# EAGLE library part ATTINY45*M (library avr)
MICROCONTROLLER 4 Kbytes FLASH 256 bytes EEPROM 256 bytes RAM 4-channel 10 bit ADC USI
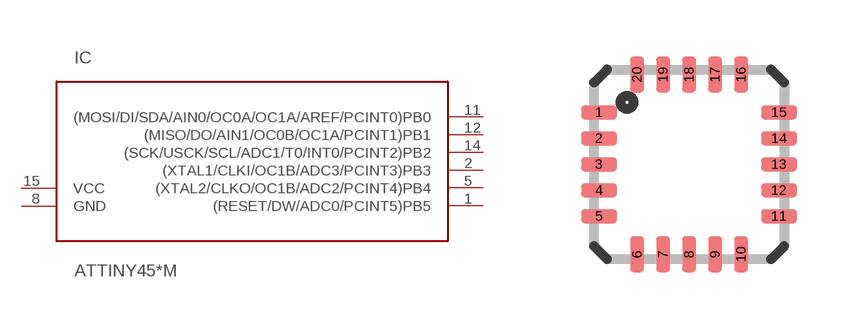
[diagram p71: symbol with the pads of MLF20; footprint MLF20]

Designator prefix IC

## ATTINY45-20M, ATTINY45V-10M  [MLF20]
1  (RESET/DW/ADC0/PCINT5)PB5
2  (XTAL1/CLKI/OC1B/ADC3/PCINT3)PB3
3  P$1  nc
4  P$2  nc
5  (XTAL2/CLKO/OC1B/ADC2/PCINT4)PB4
6  P$3  nc
7  P$4  nc
8  GND
9  P$5  nc
10  P$6  nc
11  (MOSI/DI/SDA/AIN0/OC0A/OC1A/AREF/PCINT0)PB0
12  (MISO/DO/AIN1/OC0B/OC1A/PCINT1)PB1
13  P$7  nc
14  (SCK/USCK/SCL/ADC1/T0/INT0/PCINT2)PB2
15  VCC
16  P$8  nc
17  P$9  nc
18  P$10  nc
19  P$11  nc
20  P$12  nc

## Footprint MLF20 (pad centres in mm)
HP-VFQFP-N20 Micro Lead Frame package (MLF)
smd 0.9 x 0.35: 1 -2.25,1.3; 2 -2.25,0.65; 3 -2.25,0; 4 -2.25,-0.65; 5 -2.25,-1.3; 11 2.25,-1.3; 12 2.25,-0.65; 13 2.25,0; 14 2.25,0.65; 15 2.25,1.3
smd 0.35 x 0.9: 6 -1.3,-2.25; 7 -0.65,-2.25; 8 0,-2.25; 9 0.65,-2.25; 10 1.3,-2.25; 16 1.3,2.25; 17 0.65,2.25; 18 0,2.25; 19 -0.65,2.25; 20 -1.3,2.25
